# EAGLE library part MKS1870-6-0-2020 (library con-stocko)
Serie MKS 1850 Lötstifte In-line, Raster 2.5 mm, Stiftwannen, stehend, mit Rastlasche Source: http://www.stocko.de/de/index.php?seite=ka_rfk2_mks1850.html&rubrik=Katalog+-+RFK+2 rfk_1850.pdf
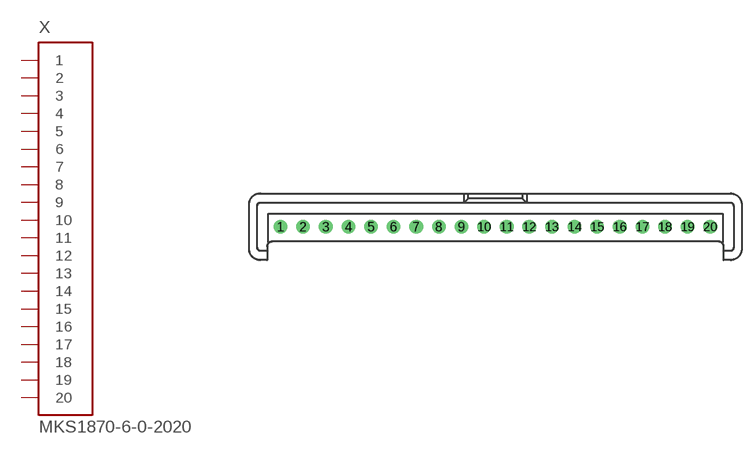
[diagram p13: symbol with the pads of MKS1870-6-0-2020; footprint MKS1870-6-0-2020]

Designator prefix X

## MKS1870-6-0-2020 (OC_FARNELL: unknown; OC_NEWARK: unknown)  [MKS1870-6-0-2020]
1  1  in
2  2  in
3  3  in
4  4  in
5  5  in
6  6  in
7  7  in
8  8  in
9  9  in
10  10  in
11  11  in
12  12  in
13  13  in
14  14  in
15  15  in
16  16  in
17  17  in
18  18  in
19  19  in
20  20  in

## Footprint MKS1870-6-0-2020 (pad centres in mm)
Serie MKS 1850 Lötstifte In-line, Raster 2.5 mm, Stiftwannen, stehend, mit Rastlasche Source: http://www.stocko.de/de/index.php?seite=ka_rfk2_mks1850.html&rubrik=Katalog+-+RFK+2 rfk_1850.pdf
drill 1 pad 1.422 round: 1 -23.75,0; 2 -21.25,0; 3 -18.75,0; 4 -16.25,0; 5 -13.75,0; 6 -11.25,0; 7 -8.75,0; 8 -6.25,0; 9 -3.75,0; 10 -1.25,0; 11 1.25,0; 12 3.75,0; 13 6.25,0; 14 8.75,0; 15 11.25,0; 16 13.75,0; 17 16.25,0; 18 18.75,0; 19 21.25,0; 20 23.75,0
